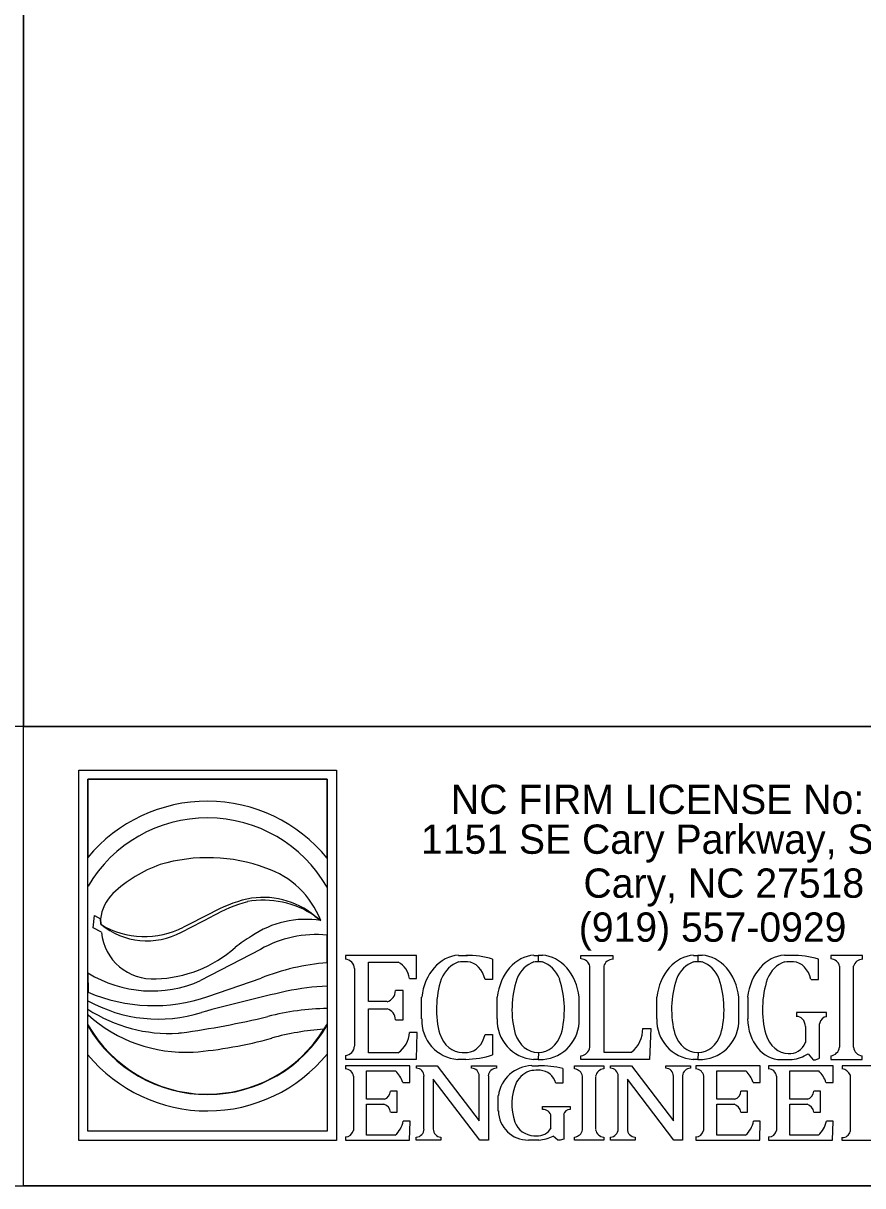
# Model space of a CAD drawing. Extents: x 1967100 to 1968800, y 964086 to 965186.
# Drawn here: x 1968674.5 to 1968747.6, y 964983.4 to 965084.7 of the extents above; entities that cross this region are included whole.
import ezdxf

# ---------------------------------------------------------------- set-up
doc = ezdxf.new("R2010")
doc.units = 0
for name, color, linetype in [('Exist Horizontal Alignment Tick Label', 7, 'Continuous'), ('Sheet Block Title CELL', 7, 'Continuous'), ('Sheet Plan And Profile CELL', 7, 'Continuous'), ('Sheet Sticker Exception Certification CELL', 7, 'Continuous')]:
    doc.layers.add(name, color=color, linetype=linetype)

msp = doc.modelspace()

# ---------------------------------------------------------------- linework, layer by layer
at = {"layer": 'Sheet Block Title CELL'}
for p, q in [((1968679.35, 965019.64), (1968701.78, 965019.64)), ((1968679.35, 964987.38), (1968679.35, 965019.64)), ((1968680.13, 964988.19), (1968680.13, 965018.85)), ((1968680.13, 965018.85), (1968700.97, 965018.85)), ((1968700.97, 965018.85), (1968680.13, 965018.85)), ((1968680.13, 965018.85), (1968680.13, 965012.02)), ((1968700.97, 965018.85), (1968700.97, 964988.19)), ((1968700.97, 965011.95), (1968700.97, 965018.85)), ((1968701.78, 965019.64), (1968701.78, 964987.38)), ((1968680.58, 965005.89), (1968680.7, 965006.98)), ((1968680.7, 965006.98), (1968681.22, 965006.68)), ((1968681.25, 965006.21), (1968681.22, 965006.68)), ((1968681.22, 965006.68), (1968681.25, 965006.21)), ((1968688.29, 965005.53), (1968690.98, 965006.91)), ((1968690.82, 965007.15), (1968688.45, 965005.96)), ((1968700.42, 965006.54), (1968699.91, 965006.93)), ((1968699.91, 965006.93), (1968700.42, 965006.54)), ((1968681.3, 965005.51), (1968680.58, 965005.89)), ((1968700.97, 965002.86), (1968700.97, 965005.26)), ((1968695.16, 965004.02), (1968689.95, 965001.3)), ((1968712.41, 965003.5), (1968713.19, 965003.5)), ((1968713.19, 965003.5), (1968713.06, 965003.5)), ((1968718.99, 965003.5), (1968719.37, 965003.5)), ((1968719.74, 965003.5), (1968719.37, 965003.5)), ((1968719.37, 965003.5), (1968719.37, 965002.95)), ((1968719.37, 965003.5), (1968719.37, 965002.95)), ((1968732.9, 965003.5), (1968733.27, 965003.5)), ((1968733.65, 965003.5), (1968733.27, 965003.5)), ((1968733.27, 965003.5), (1968733.27, 965002.95)), ((1968733.27, 965003.5), (1968733.27, 965002.95)), ((1968741.59, 965003.5), (1968740.82, 965003.5)), ((1968708.75, 965003.49), (1968702.57, 965003.49)), ((1968702.57, 965003.49), (1968702.57, 965003.16)), ((1968704.59, 964999.47), (1968704.59, 965002.92)), ((1968704.59, 965002.92), (1968707.16, 965002.92)), ((1968708.75, 965001.5), (1968708.75, 965003.49)), ((1968715.39, 965003.17), (1968715.39, 965001.39)), ((1968723.09, 965003.49), (1968725.87, 965003.49)), ((1968723.09, 965003.19), (1968723.09, 965003.49)), ((1968723.86, 964995.51), (1968723.86, 965002.56)), ((1968725.07, 965002.56), (1968725.07, 964995.08)), ((1968725.87, 965003.49), (1968725.87, 965003.15)), ((1968743.8, 965001.39), (1968743.8, 965003.17)), ((1968747.63, 965003.49), (1968744.86, 965003.49)), ((1968744.86, 965003.49), (1968744.86, 965003.19)), ((1968745.62, 965002.56), (1968745.62, 964995.51)), ((1968746.84, 964995.51), (1968746.84, 965002.56)), ((1968747.63, 965003.15), (1968747.63, 965003.49)), ((1968680.13, 965001.97), (1968680.14, 965000.29)), ((1968690.57, 964999.91), (1968695.22, 965001.52)), ((1968703.35, 965002.35), (1968703.35, 964995.61)), ((1968708.14, 965001.5), (1968708.75, 965001.5)), ((1968700.97, 965000.81), (1968700.97, 964998.87)), ((1968715.39, 965001.39), (1968714.73, 965001.39)), ((1968743.14, 965001.39), (1968743.8, 965001.39)), ((1968680.13, 964998.82), (1968680.13, 964999.56)), ((1968706.19, 964999.47), (1968704.59, 964999.47)), ((1968707.6, 965000.43), (1968706.92, 965000.43)), ((1968707.6, 964997.89), (1968707.6, 965000.43)), ((1968709.21, 964997.98), (1968709.21, 964999.85)), ((1968715.79, 964997.98), (1968715.79, 964999.85)), ((1968722.94, 964997.98), (1968722.94, 964999.85)), ((1968729.7, 964997.98), (1968729.7, 964999.85)), ((1968736.85, 964997.98), (1968736.85, 964999.85)), ((1968737.62, 964999.85), (1968737.62, 964997.98)), ((1968704.59, 964995.01), (1968704.59, 964998.84)), ((1968704.59, 964998.84), (1968706.19, 964998.84)), ((1968744.5, 964998.52), (1968741.86, 964998.52)), ((1968741.86, 964998.52), (1968741.86, 964998.16)), ((1968744.5, 964998.16), (1968744.5, 964998.52)), ((1968680.13, 964997.46), (1968680.13, 964998.31)), ((1968706.92, 964997.89), (1968707.6, 964997.89)), ((1968743.88, 964994.54), (1968743.88, 964997.54)), ((1968708.83, 964996.79), (1968708.16, 964996.79)), ((1968708.75, 964994.45), (1968708.83, 964996.79)), ((1968714.73, 964996.61), (1968715.39, 964996.61)), ((1968715.39, 964996.61), (1968715.39, 964994.84)), ((1968728.46, 964997.13), (1968729.19, 964997.13)), ((1968729.19, 964997.13), (1968729.05, 964994.44)), ((1968742.66, 964997.31), (1968742.66, 964995.92)), ((1968680.13, 964988.19), (1968680.13, 964994.96)), ((1968700.97, 964995.02), (1968700.97, 964988.19)), ((1968702.57, 964994.79), (1968702.57, 964994.45)), ((1968702.57, 964994.45), (1968708.75, 964994.45)), ((1968707.14, 964995.01), (1968704.59, 964995.01)), ((1968713.05, 964994.44), (1968712.37, 964994.44)), ((1968712.75, 964995.04), (1968713.21, 964995.05)), ((1968719.37, 964994.44), (1968718.95, 964994.44)), ((1968719.34, 964995.04), (1968719.37, 964995.04)), ((1968719.38, 964995.04), (1968719.37, 964994.44)), ((1968719.38, 964995.04), (1968719.37, 964994.44)), ((1968719.37, 964994.44), (1968719.79, 964994.44)), ((1968723.09, 964994.44), (1968723.09, 964994.76)), ((1968729.05, 964994.44), (1968723.09, 964994.44)), ((1968725.07, 964995.08), (1968727.5, 964995.08)), ((1968733.27, 964994.44), (1968732.85, 964994.44)), ((1968733.24, 964995.04), (1968733.27, 964995.04)), ((1968733.29, 964995.04), (1968733.27, 964994.44)), ((1968733.29, 964995.04), (1968733.27, 964994.44)), ((1968733.27, 964994.44), (1968733.69, 964994.44)), ((1968740.42, 964994.42), (1968741.5, 964994.42)), ((1968742.88, 964994.92), (1968743.33, 964994.4)), ((1968743.33, 964994.4), (1968743.53, 964994.4)), ((1968743.53, 964994.4), (1968743.88, 964994.54)), ((1968744.86, 964994.76), (1968744.86, 964994.44)), ((1968744.86, 964994.44), (1968747.6, 964994.44)), ((1968747.6, 964994.44), (1968747.6, 964994.76)), ((1968708.19, 964993.89), (1968702.56, 964993.89)), ((1968702.56, 964993.89), (1968702.56, 964993.6)), ((1968704.4, 964990.96), (1968704.4, 964993.43)), ((1968704.4, 964993.43), (1968706.94, 964993.43)), ((1968708.19, 964992.42), (1968708.19, 964993.89)), ((1968708.75, 964993.67), (1968708.75, 964993.89)), ((1968708.75, 964993.89), (1968710.57, 964993.89)), ((1968710.57, 964993.89), (1968714.23, 964989.09)), ((1968713.56, 964993.67), (1968713.56, 964993.89)), ((1968713.56, 964993.89), (1968715.72, 964993.89)), ((1968715.72, 964993.89), (1968715.72, 964993.67)), ((1968718.8, 964993.89), (1968719.39, 964993.89)), ((1968721.51, 964993.65), (1968721.51, 964992.38)), ((1968722.54, 964993.89), (1968725.07, 964993.89)), ((1968722.54, 964993.61), (1968722.54, 964993.89)), ((1968725.07, 964993.89), (1968725.07, 964993.61)), ((1968725.67, 964993.67), (1968725.67, 964993.89)), ((1968725.67, 964993.89), (1968727.5, 964993.89)), ((1968727.5, 964993.89), (1968731.15, 964989.09)), ((1968730.48, 964993.67), (1968730.48, 964993.89)), ((1968730.48, 964993.89), (1968732.64, 964993.89)), ((1968732.64, 964993.89), (1968732.64, 964993.67)), ((1968738.71, 964993.89), (1968733.09, 964993.89)), ((1968733.09, 964993.89), (1968733.09, 964993.6)), ((1968734.93, 964990.96), (1968734.93, 964993.43)), ((1968734.93, 964993.43), (1968737.46, 964993.43)), ((1968738.71, 964992.42), (1968738.71, 964993.89)), ((1968745.07, 964993.89), (1968739.44, 964993.89)), ((1968739.44, 964993.89), (1968739.44, 964993.6)), ((1968741.28, 964990.96), (1968741.28, 964993.43)), ((1968741.28, 964993.43), (1968743.82, 964993.43)), ((1968745.07, 964992.42), (1968745.07, 964993.89)), ((1968748.91, 964993.89), (1968745.85, 964993.89)), ((1968745.85, 964993.89), (1968745.85, 964993.6)), ((1968703.26, 964992.99), (1968703.26, 964988.25)), ((1968707.57, 964992.42), (1968708.19, 964992.42)), ((1968709.41, 964988.37), (1968709.41, 964992.98)), ((1968714.27, 964987.39), (1968710.21, 964992.72)), ((1968710.21, 964992.72), (1968710.21, 964988.37)), ((1968714.23, 964989.09), (1968714.23, 964992.98)), ((1968715.02, 964993.01), (1968715.02, 964987.39)), ((1968721.51, 964992.38), (1968720.91, 964992.38)), ((1968723.22, 964988.3), (1968723.22, 964992.98)), ((1968724.36, 964992.96), (1968724.36, 964988.32)), ((1968726.34, 964988.37), (1968726.34, 964992.98)), ((1968731.19, 964987.39), (1968727.14, 964992.72)), ((1968727.14, 964992.72), (1968727.14, 964988.37)), ((1968731.15, 964989.09), (1968731.15, 964992.98)), ((1968731.94, 964993.01), (1968731.94, 964987.39)), ((1968733.78, 964992.99), (1968733.78, 964988.25)), ((1968738.09, 964992.42), (1968738.71, 964992.42)), ((1968740.14, 964992.99), (1968740.14, 964988.25)), ((1968744.45, 964992.42), (1968745.07, 964992.42)), ((1968746.55, 964993.08), (1968746.55, 964988.17)), ((1968707.09, 964991.67), (1968706.5, 964991.67)), ((1968707.09, 964989.85), (1968707.09, 964991.67)), ((1968737.61, 964991.67), (1968737.02, 964991.67)), ((1968737.61, 964989.85), (1968737.61, 964991.67)), ((1968743.96, 964991.67), (1968743.38, 964991.67)), ((1968743.96, 964989.85), (1968743.96, 964991.67)), ((1968705.95, 964990.96), (1968704.4, 964990.96)), ((1968704.4, 964987.83), (1968704.4, 964990.53)), ((1968704.4, 964990.53), (1968705.92, 964990.53)), ((1968715.89, 964989.94), (1968715.89, 964991.28)), ((1968719.75, 964990.08), (1968719.75, 964990.33)), ((1968719.75, 964990.33), (1968722.14, 964990.33)), ((1968722.14, 964990.33), (1968722.14, 964990.08)), ((1968736.47, 964990.96), (1968734.93, 964990.96)), ((1968734.93, 964987.83), (1968734.93, 964990.53)), ((1968734.93, 964990.53), (1968736.44, 964990.53)), ((1968742.83, 964990.96), (1968741.28, 964990.96)), ((1968741.28, 964987.83), (1968741.28, 964990.53)), ((1968741.28, 964990.53), (1968742.79, 964990.53)), ((1968706.51, 964989.85), (1968707.09, 964989.85)), ((1968720.48, 964988.48), (1968720.48, 964989.47)), ((1968721.59, 964989.64), (1968721.59, 964987.49)), ((1968737.03, 964989.85), (1968737.61, 964989.85)), ((1968743.38, 964989.85), (1968743.96, 964989.85)), ((1968708.2, 964989.06), (1968707.61, 964989.06)), ((1968708.14, 964987.39), (1968708.2, 964989.06)), ((1968738.72, 964989.06), (1968738.13, 964989.06)), ((1968738.67, 964987.39), (1968738.72, 964989.06)), ((1968745.08, 964989.06), (1968744.49, 964989.06)), ((1968745.02, 964987.39), (1968745.08, 964989.06)), ((1968701.78, 964987.38), (1968679.35, 964987.38)), ((1968700.97, 964988.19), (1968680.13, 964988.19)), ((1968700.97, 964988.19), (1968680.13, 964988.19)), ((1968702.56, 964987.68), (1968702.56, 964987.39)), ((1968702.56, 964987.39), (1968708.14, 964987.39)), ((1968706.91, 964987.83), (1968704.4, 964987.83)), ((1968708.74, 964987.39), (1968708.74, 964987.67)), ((1968710.89, 964987.39), (1968708.74, 964987.39)), ((1968710.89, 964987.67), (1968710.89, 964987.39)), ((1968715.02, 964987.39), (1968714.27, 964987.39)), ((1968719.43, 964987.4), (1968718.51, 964987.4)), ((1968718.98, 964987.79), (1968719.21, 964987.78)), ((1968721.08, 964987.39), (1968720.68, 964987.76)), ((1968721.27, 964987.39), (1968721.08, 964987.39)), ((1968721.59, 964987.49), (1968721.27, 964987.39)), ((1968722.54, 964987.39), (1968722.54, 964987.67)), ((1968725.07, 964987.39), (1968722.54, 964987.39)), ((1968725.07, 964987.67), (1968725.07, 964987.39)), ((1968725.67, 964987.39), (1968725.67, 964987.67)), ((1968727.81, 964987.39), (1968725.67, 964987.39)), ((1968727.81, 964987.67), (1968727.81, 964987.39)), ((1968731.94, 964987.39), (1968731.19, 964987.39)), ((1968733.09, 964987.68), (1968733.09, 964987.39)), ((1968733.09, 964987.39), (1968738.67, 964987.39)), ((1968737.43, 964987.83), (1968734.93, 964987.83)), ((1968739.44, 964987.68), (1968739.44, 964987.39)), ((1968739.44, 964987.39), (1968745.02, 964987.39)), ((1968743.79, 964987.83), (1968741.28, 964987.83)), ((1968745.83, 964987.63), (1968745.83, 964987.39)), ((1968745.83, 964987.39), (1968748.37, 964987.39))]:
    msp.add_line(p, q, dxfattribs=at)
for centre, radius, start, end in [((1968690.53, 965003.44), 13.49, 39.2542, 140.4372), ((1968690.53, 965003.44), 12.04, 29.8701, 149.6922), ((1968690.57, 964997.34), 14.67, 69.7851, 106.409), ((1968690.42, 965000.25), 11.86, 109.6708, 133.2217), ((1968693.16, 965003.73), 7.78, 21.1513, 71.4679), ((1968684.96, 965006.23), 3.76, 135.058, 173.1815), ((1968697.12, 964995.82), 12.97, 103.9821, 119.0512), ((1968698.07, 964994.2), 14.55, 106.1052, 119.1611), ((1968695.41, 965001.5), 7.05, 50.3583, 101.6336), ((1968695.43, 965000.36), 7.95, 55.7305, 100.1537), ((1968699.11, 964998.31), 8.33, 80.947, 124.5909), ((1968685.08, 965012.54), 7.4, 238.8696, 297.1346), ((1968685.27, 965011.1), 6.33, 230.537, 298.4622), ((1968685.78, 965005.95), 4.5, 185.6662, 273.7982), ((1968700.99, 964993.95), 13.02, 120.5, 128.1006), ((1968700, 964995.58), 9.73, 84.273, 119.8435), ((1968685.75, 965012.28), 10.83, 271.6963, 311.667), ((1968702.52, 964983.24), 19.68, 94.518, 111.7969), ((1968702.53, 965002.34), 0.822, 0.3623, 87.1736), ((1968706.34, 965001.3), 1.81, 6.1084, 62.9651), ((1968723.08, 965002.39), 0.8, 12.3089, 88.7423), ((1968725.88, 965002.31), 0.847, 91.1208, 162.9275), ((1968744.84, 965002.39), 0.8, 12.3089, 88.7423), ((1968747.65, 965002.31), 0.847, 91.1208, 162.9275), ((1968685.68, 965010.99), 10.59, 238.4239, 293.7777), ((1968701.88, 964978.68), 22.15, 92.3429, 101.574), ((1968686.29, 965010.59), 12.64, 240.842, 287.1607), ((1968685.85, 965013.58), 14.46, 246.7513, 289.0839), ((1968738.81, 964819.03), 186.01, 102.8534, 105.2092), ((1968705.96, 965000.4), 0.961, 283.9515, 1.7152), ((1968687.2, 965009.59), 12.89, 236.7184, 273.4672), ((1968701.41, 964976.33), 22.55, 91.0972, 104.36), ((1968705.96, 964997.91), 0.961, 358.7793, 76.0485), ((1968690.53, 965003.44), 12.06, 210.3078, 330.1299), ((1968688.66, 965007.85), 12.79, 228.2077, 272.8906), ((1968690.53, 965003.37), 11.96, 209.6341, 328.1944), ((1968677.53, 965074.77), 78.75, 277.8449, 283.4228), ((1968690.53, 965003.37), 11.96, 328.1944, 330.8772), ((1968712.62, 964997.84), 3.41, 177.7234, 265.7286), ((1968719.2, 964997.84), 3.41, 177.7234, 265.7286), ((1968719.53, 964997.84), 3.41, 274.2714, 2.2766), ((1968733.11, 964997.84), 3.41, 177.7234, 265.7286), ((1968733.44, 964997.84), 3.41, 274.2714, 2.2766), ((1968687.75, 965000.65), 3.93, 273.4672, 277.8449), ((1968702.57, 964972.47), 24.68, 94.3745, 105.1118), ((1968705.77, 964996.97), 2.4, 304.8967, 355.5398), ((1968725.98, 964997.05), 2.49, 307.6902, 1.931), ((1968686.22, 965032.12), 37.18, 274.7648, 285.4822), ((1968702.53, 964995.61), 0.822, 272.8264, 359.6377), ((1968723.02, 964995.6), 0.844, 275.0605, 353.7285), ((1968744.78, 964995.6), 0.844, 275.0605, 353.7285), ((1968747.67, 964995.6), 0.844, 186.2062, 264.9395), ((1968690.53, 965003.44), 13.49, 219.5628, 320.7458), ((1968712.92, 965002.35), 7.91, 270.9907, 288.217), ((1968702.57, 964992.9), 0.702, 7.5255, 90.2156), ((1968705.31, 964991.72), 2.36, 17.3169, 46.5226), ((1968708.72, 964992.98), 0.696, 359.9179, 87.415), ((1968713.53, 964992.98), 0.696, 359.9179, 87.415), ((1968715.73, 964992.96), 0.713, 90.7506, 175.9457), ((1968718.92, 964990.84), 3.06, 92.1486, 171.576), ((1968719.31, 964991.44), 2.1, 103.9031, 152.3401), ((1968719.3, 964987.53), 5.96, 87.8484, 94.8231), ((1968719.45, 964984.91), 8.98, 76.739, 90.3672), ((1968719.44, 964991.97), 1.52, 15.4811, 86.8261), ((1968722.44, 964992.82), 0.799, 11.6163, 82.8941), ((1968725.15, 964992.82), 0.796, 95.7655, 169.4461), ((1968725.64, 964992.98), 0.696, 359.9179, 87.415), ((1968730.45, 964992.98), 0.696, 359.9179, 87.415), ((1968732.65, 964992.96), 0.713, 90.7506, 175.9457), ((1968733.09, 964992.9), 0.702, 7.5255, 90.2156), ((1968735.84, 964991.72), 2.36, 17.3169, 46.5226), ((1968739.44, 964992.9), 0.702, 7.5255, 90.2156), ((1968742.19, 964991.72), 2.36, 17.3169, 46.5226), ((1968745.74, 964992.72), 0.889, 23.9894, 83.0425), ((1968721.94, 964990.53), 4.87, 157.2807, 198.6204), ((1968705.73, 964991.7), 0.766, 286.2755, 357.8604), ((1968736.26, 964991.7), 0.766, 286.2755, 357.8604), ((1968742.61, 964991.7), 0.766, 286.2755, 357.8604), ((1968705.68, 964989.73), 0.834, 8.2709, 73.5181), ((1968736.2, 964989.73), 0.834, 8.2709, 73.5181), ((1968742.56, 964989.73), 0.834, 8.2709, 73.5181), ((1968718.48, 964989.99), 2.58, 180.9518, 270.8413), ((1968719.81, 964989.41), 0.67, 4.7505, 95.3525), ((1968722.14, 964989.51), 0.571, 89.9165, 166.8472), ((1968705.37, 964989.51), 2.28, 312.3614, 348.427), ((1968708.72, 964988.37), 0.696, 272.0354, 0.0821), ((1968710.91, 964988.37), 0.696, 179.9179, 267.9646), ((1968719.1, 964989.7), 1.92, 202.1177, 266.4323), ((1968719.29, 964989.13), 1.36, 266.5697, 331.2289), ((1968725.15, 964988.46), 0.796, 190.5539, 264.2345), ((1968725.64, 964988.37), 0.696, 272.0354, 0.0821), ((1968727.83, 964988.37), 0.696, 179.9179, 267.9646), ((1968735.9, 964989.51), 2.28, 312.3614, 348.427), ((1968742.25, 964989.51), 2.28, 312.3614, 348.427), ((1968702.53, 964988.43), 0.75, 272.3651, 346.7666), ((1968719.09, 964990.98), 3.59, 275.4223, 296.3019), ((1968722.44, 964988.46), 0.799, 277.1059, 348.3837), ((1968733.05, 964988.43), 0.75, 272.3651, 346.7666), ((1968739.41, 964988.43), 0.75, 272.3651, 346.7666), ((1968745.87, 964988.32), 0.695, 266.8167, 347.257)]:
    msp.add_arc(centre, radius, start, end, dxfattribs=at)
for centre, major_axis, ratio, start_param, end_param in [((1968712.54, 964999.23), (0, 4.28), 0.785714, 0.0375, 1.423769), ((1968713.13, 964990.93), (0, 12.57), 0.785714, 6.051738, 6.289595), ((1968719.12, 964999.23), (0, 4.28), 0.785714, 0.0375, 1.423769), ((1968719.61, 964999.23), (0, -4.28), 0.785714, 1.717824, 3.104092), ((1968733.03, 964999.23), (0, 4.28), 0.785714, 0.0375, 1.423769), ((1968733.52, 964999.23), (0, -4.28), 0.785714, 1.717824, 3.104092), ((1968740.94, 964999.23), (0, 4.28), 0.785714, 0.0375, 1.423769), ((1968741.53, 964990.93), (0, 12.57), 0.785714, 6.051738, 6.289595), ((1968712.97, 965000.07), (0, 2.94), 0.785714, 0.242655, 1.08804), ((1968712.96, 964994.6), (0, 8.35), 0.785714, 6.245633, 6.367364), ((1968713.12, 965000.82), (0, 2.13), 0.785714, 4.982585, 6.22779), ((1968719.55, 965000.07), (0, 2.94), 0.785714, 0.242655, 1.08804), ((1968719.55, 964994.6), (0, 8.35), 0.785714, 0.027164, 0.084179), ((1968719.19, 964994.6), (0, -8.35), 0.785714, 3.057414, 3.114429), ((1968719.19, 965000.07), (0, -2.94), 0.785714, 2.053552, 2.898937), ((1968733.46, 965000.07), (0, 2.94), 0.785714, 0.242655, 1.08804), ((1968733.45, 964994.6), (0, 8.35), 0.785714, 0.027164, 0.084179), ((1968733.1, 964994.6), (0, -8.35), 0.785714, 3.057414, 3.114429), ((1968733.09, 965000.07), (0, -2.94), 0.785714, 2.053552, 2.898937), ((1968741.37, 965000.07), (0, 2.94), 0.785714, 0.242655, 1.08804), ((1968741.37, 964994.6), (0, 8.35), 0.785714, 6.245633, 6.367364), ((1968741.52, 965000.82), (0, 2.13), 0.785714, 4.982585, 6.22779), ((1968715.86, 964998.8), (0, 6.82), 0.785714, 1.17427, 1.895784), ((1968722.44, 964998.8), (0, 6.82), 0.785714, 1.17427, 1.895784), ((1968716.29, 964998.8), (0, -6.82), 0.785714, 1.245809, 1.967323), ((1968736.35, 964998.8), (0, 6.82), 0.785714, 1.17427, 1.895784), ((1968730.2, 964998.8), (0, -6.82), 0.785714, 1.245809, 1.967323), ((1968744.27, 964998.8), (0, 6.82), 0.785714, 1.17427, 1.895784), ((1968740.46, 964998.04), (0, 3.62), 0.785714, 1.587409, 3.156276), ((1968741.93, 964997.23), (0, 0.938), 0.785714, 4.7953, 6.376605), ((1968744.49, 964997.36), (0, 0.799), 0.785714, 6.281728, 7.624421), ((1968712.74, 964997.64), (0, 2.59), 0.812926, 1.956822, 3.148618), ((1968713.12, 964997.18), (0, 2.13), 0.785714, 3.196988, 4.442193), ((1968719.32, 964997.64), (0, 2.59), 0.812926, 1.956822, 3.148618), ((1968719.41, 964997.64), (0, -2.59), 0.812926, 6.27616, 7.467956), ((1968733.23, 964997.64), (0, 2.59), 0.812926, 1.956822, 3.148618), ((1968733.32, 964997.64), (0, -2.59), 0.812926, 6.27616, 7.467956), ((1968741.15, 964997.64), (0, 2.68), 0.785714, 1.956822, 3.148618), ((1968741.35, 964996.84), (0, 1.9), 0.785714, 3.012278, 4.210239), ((1968741.13, 964999.43), (0, 5.03), 0.785714, 3.23623, 3.600647)]:
    msp.add_ellipse(centre, major_axis=major_axis, ratio=ratio, start_param=start_param, end_param=end_param, dxfattribs=at)
at = {"layer": 'Sheet Plan And Profile CELL'}
msp.add_line((1968674.52, 965135.93), (1968674.52, 965023.48), dxfattribs=at)
for points in [[(1968574.47, 965135.93), (1968674.52, 965135.93), (1968674.52, 965023.43), (1968574.47, 965023.43)], [(1968674.52, 965135.93), (1968774.52, 965135.93), (1968774.52, 965023.43), (1968674.52, 965023.43)], [(1968674.52, 965023.43), (1968774.52, 965023.43), (1968774.52, 964983.43), (1968674.52, 964983.43)]]:
    msp.add_lwpolyline(points, close=True, dxfattribs=at)
at = {"layer": 'Sheet Sticker Exception Certification CELL'}
msp.add_line((1968574.48, 964983.43), (1968774.52, 964983.43), dxfattribs=at)

# ---------------------------------------------------------------- texts
at = {"layer": 'Exist Horizontal Alignment Tick Label'}
for s, p in [('NC FIRM LICENSE No: F-1148', (1968711.76, 965015.82)), ('1151 SE Cary Parkway, Suite 101', (1968709.15, 965012.35)), ('Cary, NC 27518', (1968723.31, 965008.52)), ('(919) 557-0929', (1968722.9, 965004.69))]:
    msp.add_text(s, height=2.5507, rotation=360, dxfattribs=at).set_placement(p)

doc.saveas('drawing.dxf')
